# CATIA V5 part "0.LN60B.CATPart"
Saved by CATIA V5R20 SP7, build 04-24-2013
Part number: 0.LN60B
Material "Nessuno"
Bounding box of the stored display mesh (mm): x 0 to 150.807, y -124.685 to 0, z -91.151 to 75.737
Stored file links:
  C:\Users\designer2\Desktop\Ottobre 2022\25-10-2022\04\Yori Evo 48V\0.LN60B.CATPart
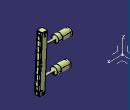
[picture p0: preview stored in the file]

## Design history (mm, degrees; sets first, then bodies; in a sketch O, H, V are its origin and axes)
AxisSystem1: origin (0, 0, 0), X (1, 0, 0), Y (0, 1, 0), Z (0, 0, 1)
Set1
  DatumSurface1
Body1 (main body), material "Nessuno"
